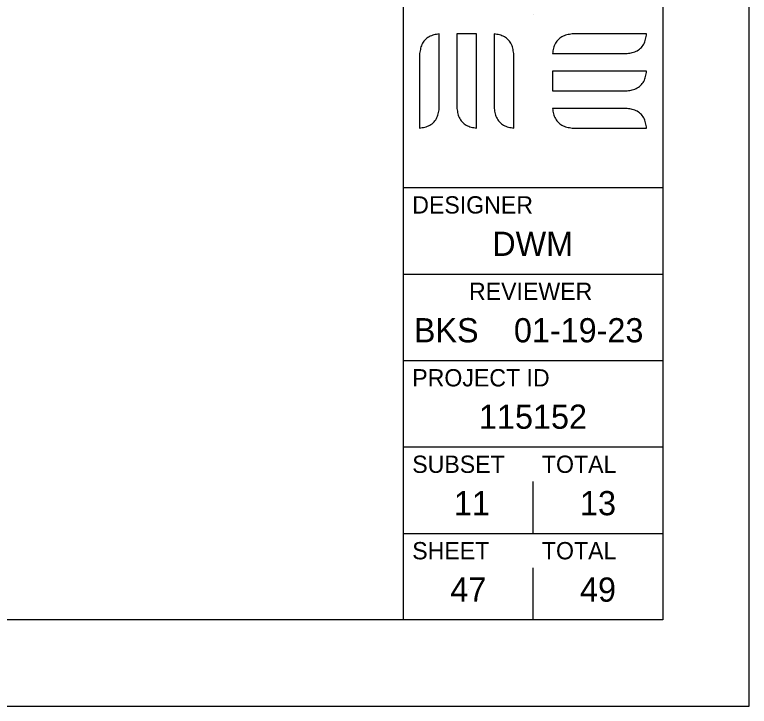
# Model space of a CAD drawing. Extents: x 0 to 34, y -0.1 to 22.
# Drawn here: x 29.75 to 34, y 0 to 4 of the extents above; entities that cross this region are included whole.
import ezdxf

# ---------------------------------------------------------------- set-up
doc = ezdxf.new("R2010")
doc.units = 0
for name, color, linetype in [('1', 7, 'Continuous'), ('2', 7, 'Continuous'), ('3', 7, 'Continuous'), ('4', 7, 'Continuous')]:
    doc.layers.add(name, color=color, linetype=linetype)

msp = doc.modelspace()

# ---------------------------------------------------------------- linework, layer by layer
at = {"layer": '1'}
msp.add_lwpolyline([(0, 0), (34, 0), (34, 22), (0, 22)], close=True, dxfattribs=at)
at = {"layer": '2'}
for p, q in [((32.75, 4), (32.75, 4)), ((32.75, 1), (32.75, 1.3)), ((32.75, 0.5), (32.75, 0.8)), ((32.375, 0.675), (32.375, 0.675))]:
    msp.add_line(p, q, dxfattribs=at)
at = {"layer": '3'}
for p, q in [((32, 0.5), (32, 21.5)), ((32, 3), (33.5, 3)), ((32, 2.5), (33.5, 2.5)), ((32, 2), (33.5, 2)), ((32, 1.5), (33.5, 1.5)), ((32, 1), (33.5, 1))]:
    msp.add_line(p, q, dxfattribs=at)
msp.add_lwpolyline([(1.5, 21.5), (33.5, 21.5), (33.5, 0.5), (1.5, 0.5)], close=True, dxfattribs=at)
at = {"layer": '4'}
for points in [[(32.2061, 3.8887), (32.1984, 3.8875), (32.1907, 3.8862), (32.1831, 3.8847), (32.1756, 3.883), (32.1683, 3.881), (32.1611, 3.8786), (32.154, 3.8758), (32.1472, 3.8723), (32.1406, 3.8683), (32.1344, 3.8637), (32.1284, 3.8587), (32.1229, 3.8531), (32.1179, 3.8472), (32.1133, 3.841), (32.1093, 3.8344), (32.1058, 3.8276), (32.103, 3.8205), (32.1006, 3.8133), (32.0985, 3.8059), (32.0968, 3.7984), (32.0954, 3.7909), (32.0941, 3.7832), (32.0929, 3.7755), (32.0929, 3.3444), (32.1006, 3.3456), (32.1082, 3.3469), (32.1158, 3.3483), (32.1233, 3.35), (32.1307, 3.352), (32.1379, 3.3544), (32.1449, 3.3573), (32.1517, 3.3608), (32.1583, 3.3648), (32.1646, 3.3693), (32.1705, 3.3744), (32.176, 3.3799), (32.1811, 3.3859), (32.1856, 3.3921), (32.1897, 3.3987), (32.1931, 3.4055), (32.196, 3.4125), (32.1984, 3.4198), (32.2004, 3.4271), (32.2021, 3.4346), (32.2035, 3.4422), (32.2048, 3.4499), (32.2061, 3.4575), (32.2061, 3.8887)], [(32.4216, 3.8887), (32.3085, 3.8887), (32.3085, 3.4575), (32.3097, 3.4499), (32.311, 3.4422), (32.3124, 3.4346), (32.3141, 3.4271), (32.3161, 3.4198), (32.3185, 3.4125), (32.3214, 3.4055), (32.3249, 3.3987), (32.3289, 3.3921), (32.3334, 3.3859), (32.3385, 3.3799), (32.344, 3.3744), (32.35, 3.3693), (32.3562, 3.3648), (32.3628, 3.3608), (32.3696, 3.3573), (32.3766, 3.3544), (32.3839, 3.352), (32.3912, 3.35), (32.3987, 3.3483), (32.4063, 3.3469), (32.414, 3.3456), (32.4216, 3.3444), (32.4216, 3.8887)], [(32.6372, 3.7755), (32.636, 3.7832), (32.6347, 3.7909), (32.6333, 3.7984), (32.6316, 3.8059), (32.6296, 3.8133), (32.6271, 3.8205), (32.6243, 3.8276), (32.6208, 3.8344), (32.6168, 3.841), (32.6122, 3.8472), (32.6072, 3.8531), (32.6017, 3.8587), (32.5957, 3.8637), (32.5895, 3.8683), (32.5829, 3.8723), (32.5761, 3.8758), (32.569, 3.8786), (32.5618, 3.881), (32.5545, 3.883), (32.547, 3.8847), (32.5394, 3.8862), (32.5317, 3.8875), (32.524, 3.8887), (32.524, 3.4575), (32.5253, 3.4499), (32.5266, 3.4422), (32.528, 3.4346), (32.5297, 3.4271), (32.5317, 3.4198), (32.5341, 3.4125), (32.537, 3.4055), (32.5404, 3.3987), (32.5445, 3.3921), (32.549, 3.3859), (32.5541, 3.3799), (32.5596, 3.3744), (32.5655, 3.3693), (32.5718, 3.3648), (32.5784, 3.3608), (32.5852, 3.3573), (32.5922, 3.3544), (32.5994, 3.352), (32.6068, 3.35), (32.6143, 3.3483), (32.6219, 3.3469), (32.6295, 3.3456), (32.6372, 3.3444), (32.6372, 3.7755)], [(33.381, 3.817), (33.3855, 3.8233), (33.3896, 3.8299), (33.393, 3.8367), (33.3959, 3.8437), (33.3983, 3.8509), (33.4003, 3.8583), (33.402, 3.8658), (33.4034, 3.8734), (33.4047, 3.881), (33.406, 3.8887), (32.9748, 3.8887), (32.9671, 3.8875), (32.9595, 3.8862), (32.9519, 3.8847), (32.9444, 3.883), (32.937, 3.881), (32.9298, 3.8786), (32.9228, 3.8758), (32.9159, 3.8723), (32.9094, 3.8683), (32.9031, 3.8637), (32.8972, 3.8587), (32.8917, 3.8531), (32.8866, 3.8472), (32.882, 3.841), (32.878, 3.8344), (32.8746, 3.8276), (32.8717, 3.8205), (32.8693, 3.8133), (32.8673, 3.8059), (32.8656, 3.7984), (32.8641, 3.7909), (32.8628, 3.7832), (32.8616, 3.7755), (33.2928, 3.7755), (33.3005, 3.7767), (33.3081, 3.778), (33.3157, 3.7795), (33.3232, 3.7812), (33.3306, 3.7832), (33.3378, 3.7856), (33.3448, 3.7885), (33.3516, 3.7919), (33.3582, 3.7959), (33.3645, 3.8005), (33.3704, 3.8056), (33.3759, 3.8111), (33.381, 3.817)], [(33.3959, 3.6281), (33.3983, 3.6353), (33.4003, 3.6427), (33.402, 3.6502), (33.4034, 3.6578), (33.4047, 3.6654), (33.406, 3.6731), (32.8616, 3.6731), (32.8616, 3.5599), (33.2928, 3.5599), (33.3005, 3.5612), (33.3081, 3.5625), (33.3157, 3.5639), (33.3232, 3.5656), (33.3306, 3.5676), (33.3378, 3.57), (33.3448, 3.5729), (33.3516, 3.5763), (33.3582, 3.5804), (33.3645, 3.5849), (33.3704, 3.59), (33.3759, 3.5955), (33.381, 3.6014), (33.3855, 3.6077), (33.3896, 3.6143), (33.393, 3.6211), (33.3959, 3.6281)], [(33.3983, 3.3821), (33.3959, 3.3894), (33.393, 3.3964), (33.3896, 3.4032), (33.3855, 3.4098), (33.381, 3.4161), (33.3759, 3.422), (33.3704, 3.4275), (33.3645, 3.4326), (33.3582, 3.4371), (33.3516, 3.4412), (33.3448, 3.4446), (33.3378, 3.4475), (33.3306, 3.4499), (33.3232, 3.4519), (33.3157, 3.4536), (33.3081, 3.455), (33.3005, 3.4563), (33.2928, 3.4575), (32.8616, 3.4575), (32.8628, 3.4499), (32.8641, 3.4422), (32.8656, 3.4346), (32.8673, 3.4271), (32.8693, 3.4198), (32.8717, 3.4125), (32.8746, 3.4055), (32.878, 3.3987), (32.882, 3.3921), (32.8866, 3.3859), (32.8917, 3.3799), (32.8972, 3.3744), (32.9031, 3.3693), (32.9094, 3.3648), (32.9159, 3.3608), (32.9228, 3.3573), (32.9298, 3.3544), (32.937, 3.352), (32.9444, 3.35), (32.9519, 3.3483), (32.9595, 3.3469), (32.9671, 3.3456), (32.9748, 3.3444), (33.406, 3.3444), (33.4047, 3.352), (33.4034, 3.3597), (33.402, 3.3673), (33.4003, 3.3748), (33.3983, 3.3821)]]:
    msp.add_lwpolyline(points, dxfattribs=at)

# ---------------------------------------------------------------- texts
at = {"layer": '2'}
for s, height, p in [('DESIGNER', 0.1, (32.05, 2.85)), ('DWM', 0.14, (32.5129, 2.605)), ('REVIEWER', 0.1, (32.3783, 2.35)), ('BKS', 0.14, (32.0594, 2.105)), ('01-19-23', 0.14, (32.6381, 2.105)), ('PROJECT ID', 0.1, (32.05, 1.85)), ('115152', 0.14, (32.4362, 1.605)), ('SUBSET', 0.1, (32.05, 1.35)), ('TOTAL', 0.1, (32.8, 1.35)), ('11', 0.14, (32.2915, 1.105)), ('13', 0.14, (33.0207, 1.105)), ('SHEET', 0.1, (32.05, 0.85)), ('TOTAL', 0.1, (32.8, 0.85)), ('47', 0.14, (32.2707, 0.605)), ('49', 0.14, (33.0206, 0.605))]:
    msp.add_text(s, height=height, dxfattribs=at).set_placement(p)

doc.saveas('drawing.dxf')
